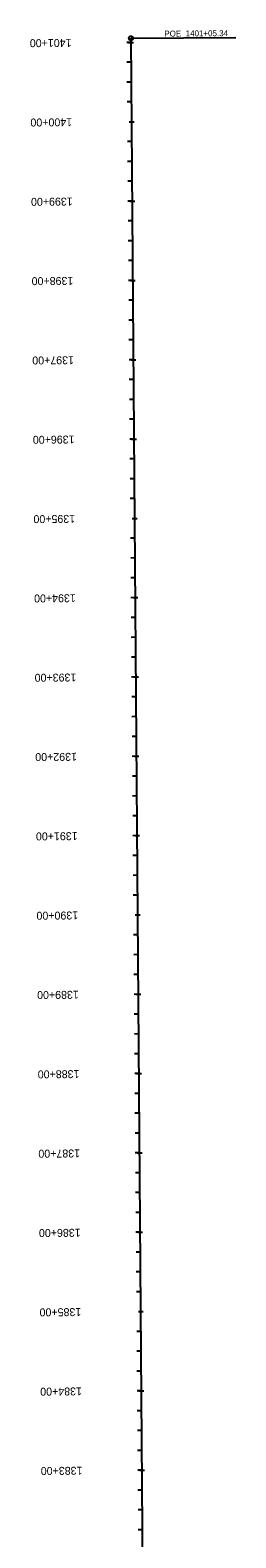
# Model space of a CAD drawing. Extents: x 19548215 to 19548727, y 7547983 to 7562114.
# Drawn here: x 19548234 to 19548493, y 7560213 to 7562114 of the extents above; entities that cross this region are included whole.
import ezdxf

# ---------------------------------------------------------------- set-up
doc = ezdxf.new("R2010")
doc.units = 0
for name, color, linetype in [('Contours Major', 7, 'Continuous'), ('Contours Minor', 7, 'Continuous'), ('TextAlignment', 7, 'Continuous'), ('TextAlignmentSml', 7, 'Continuous')]:
    doc.layers.add(name, color=color, linetype=linetype)

msp = doc.modelspace()

# ---------------------------------------------------------------- linework, layer by layer
at = {"layer": 'Contours Major'}
for p, q in [((19548360.7, 7562098.6), (19548355.3, 7562098.5)), ((19548358.4, 7561998.5), (19548364.5, 7561998.6)), ((19548362.3, 7561898.6), (19548356.8, 7561898.5)), ((19548363, 7561798.6), (19548357.6, 7561798.5)), ((19548363.8, 7561698.6), (19548358.3, 7561698.5)), ((19548364.6, 7561598.6), (19548359.1, 7561598.5)), ((19548362.3, 7561498.5), (19548368.4, 7561498.6)), ((19548366.1, 7561398.6), (19548360.6, 7561398.5)), ((19548366.9, 7561298.6), (19548361.4, 7561298.5)), ((19548367.6, 7561198.6), (19548362.2, 7561198.5)), ((19548368.4, 7561098.6), (19548363, 7561098.5)), ((19548366.1, 7560998.6), (19548372.2, 7560998.6)), ((19548370, 7560898.6), (19548364.5, 7560898.5)), ((19548370.7, 7560798.6), (19548365.3, 7560798.6)), ((19548371.5, 7560698.6), (19548366, 7560698.6)), ((19548372.3, 7560598.6), (19548366.8, 7560598.6)), ((19548370, 7560498.6), (19548376.1, 7560498.6)), ((19548373.8, 7560398.6), (19548368.3, 7560398.6)), ((19548374.6, 7560298.6), (19548369.1, 7560298.6))]:
    msp.add_line(p, q, dxfattribs=at)
at = {"layer": 'Contours Minor'}
msp.add_line((19548386.5, 7558748.2), (19548360.7, 7562103.9), dxfattribs=at)
at = {"layer": 'TextAlignment'}
for p in [(19548360.7, 7562103.9), (19548492.7, 7562104.9)]:
    msp.add_line(p, (19548492.7, 7562104.9), dxfattribs=at)
msp.add_circle((19548360.7, 7562103.9), 2.67, dxfattribs=at)
at = {"layer": 'TextAlignmentSml'}
for p, q in [((19548357.7, 7562098.5), (19548363.8, 7562098.6)), ((19548360.9, 7562073.6), (19548355.4, 7562073.5)), ((19548361.1, 7562048.6), (19548355.6, 7562048.5)), ((19548361.3, 7562023.6), (19548355.8, 7562023.5)), ((19548358.4, 7561998.5), (19548364.5, 7561998.6)), ((19548361.7, 7561973.6), (19548356.2, 7561973.5)), ((19548361.9, 7561948.6), (19548356.4, 7561948.5)), ((19548362.1, 7561923.6), (19548356.6, 7561923.5)), ((19548359.2, 7561898.5), (19548365.3, 7561898.6)), ((19548362.4, 7561873.6), (19548357, 7561873.5)), ((19548362.6, 7561848.6), (19548357.2, 7561848.5)), ((19548362.8, 7561823.6), (19548357.4, 7561823.5)), ((19548360, 7561798.5), (19548366.1, 7561798.6)), ((19548363.2, 7561773.6), (19548357.8, 7561773.5)), ((19548363.4, 7561748.6), (19548358, 7561748.5)), ((19548363.6, 7561723.6), (19548358.1, 7561723.5)), ((19548360.7, 7561698.5), (19548366.9, 7561698.6)), ((19548364, 7561673.6), (19548358.5, 7561673.5)), ((19548364.2, 7561648.6), (19548358.7, 7561648.5)), ((19548364.4, 7561623.6), (19548358.9, 7561623.5)), ((19548361.5, 7561598.5), (19548367.6, 7561598.6)), ((19548364.8, 7561573.6), (19548359.3, 7561573.5)), ((19548365, 7561548.6), (19548359.5, 7561548.5)), ((19548365.1, 7561523.6), (19548359.7, 7561523.5)), ((19548362.3, 7561498.5), (19548368.4, 7561498.6)), ((19548365.5, 7561473.6), (19548360.1, 7561473.5)), ((19548365.7, 7561448.6), (19548360.3, 7561448.5)), ((19548365.9, 7561423.6), (19548360.5, 7561423.5)), ((19548363, 7561398.6), (19548369.2, 7561398.6)), ((19548366.3, 7561373.6), (19548360.8, 7561373.5)), ((19548366.5, 7561348.6), (19548361, 7561348.5)), ((19548366.7, 7561323.6), (19548361.2, 7561323.5)), ((19548363.8, 7561298.6), (19548369.9, 7561298.6)), ((19548367.1, 7561273.6), (19548361.6, 7561273.5)), ((19548367.3, 7561248.6), (19548361.8, 7561248.5)), ((19548367.5, 7561223.6), (19548362, 7561223.5)), ((19548364.6, 7561198.6), (19548370.7, 7561198.6)), ((19548367.8, 7561173.6), (19548362.4, 7561173.5)), ((19548368, 7561148.6), (19548362.6, 7561148.5)), ((19548368.2, 7561123.6), (19548362.8, 7561123.5)), ((19548365.4, 7561098.6), (19548371.5, 7561098.6)), ((19548368.6, 7561073.6), (19548363.1, 7561073.5)), ((19548368.8, 7561048.6), (19548363.3, 7561048.5)), ((19548369, 7561023.6), (19548363.5, 7561023.5)), ((19548366.1, 7560998.6), (19548372.2, 7560998.6)), ((19548369.4, 7560973.6), (19548363.9, 7560973.5)), ((19548369.6, 7560948.6), (19548364.1, 7560948.5)), ((19548369.8, 7560923.6), (19548364.3, 7560923.5)), ((19548366.9, 7560898.6), (19548373, 7560898.6)), ((19548370.1, 7560873.6), (19548364.7, 7560873.5)), ((19548370.3, 7560848.6), (19548364.9, 7560848.5)), ((19548370.5, 7560823.6), (19548365.1, 7560823.5)), ((19548367.7, 7560798.6), (19548373.8, 7560798.6)), ((19548370.9, 7560773.6), (19548365.5, 7560773.6)), ((19548371.1, 7560748.6), (19548365.6, 7560748.6)), ((19548371.3, 7560723.6), (19548365.8, 7560723.6)), ((19548368.4, 7560698.6), (19548374.6, 7560698.6)), ((19548371.7, 7560673.6), (19548366.2, 7560673.6)), ((19548371.9, 7560648.6), (19548366.4, 7560648.6)), ((19548372.1, 7560623.6), (19548366.6, 7560623.6)), ((19548369.2, 7560598.6), (19548375.3, 7560598.6)), ((19548372.5, 7560573.6), (19548367, 7560573.6)), ((19548372.6, 7560548.6), (19548367.2, 7560548.6)), ((19548372.8, 7560523.6), (19548367.4, 7560523.6)), ((19548370, 7560498.6), (19548376.1, 7560498.6)), ((19548373.2, 7560473.6), (19548367.8, 7560473.6)), ((19548373.4, 7560448.6), (19548368, 7560448.6)), ((19548373.6, 7560423.6), (19548368.2, 7560423.6)), ((19548370.7, 7560398.6), (19548376.9, 7560398.6)), ((19548374, 7560373.6), (19548368.5, 7560373.6)), ((19548374.2, 7560348.6), (19548368.7, 7560348.6)), ((19548374.4, 7560323.6), (19548368.9, 7560323.6)), ((19548371.5, 7560298.6), (19548377.6, 7560298.6)), ((19548374.8, 7560273.6), (19548369.3, 7560273.6)), ((19548375, 7560248.6), (19548369.5, 7560248.6)), ((19548375.1, 7560223.6), (19548369.7, 7560223.6))]:
    msp.add_line(p, q, dxfattribs=at)

# ---------------------------------------------------------------- texts
at = {"layer": 'Contours Major'}
for s, p in [('1400+00', (19548286.5, 7562003)), ('1395+00', (19548290.3, 7561503)), ('1390+00', (19548294.1, 7561003)), ('1385+00', (19548298, 7560503))]:
    msp.add_text(s, height=10.02, rotation=180.441, dxfattribs=at).set_placement(p)
at = {"layer": 'TextAlignment'}
for s, p in [('POE ', (19548402.7, 7562105.9)), ('1401+05.34', (19548429.6, 7562106.1))]:
    msp.add_text(s, height=7.5, rotation=0.441, dxfattribs=at).set_placement(p)
at = {"layer": 'TextAlignmentSml'}
for s, p in [('1401+00', (19548285.7, 7562103)), ('1400+00', (19548286.5, 7562003)), ('1399+00', (19548287.2, 7561903)), ('1398+00', (19548288, 7561803)), ('1397+00', (19548288.8, 7561703)), ('1396+00', (19548289.5, 7561603)), ('1395+00', (19548290.3, 7561503)), ('1394+00', (19548291.1, 7561403)), ('1393+00', (19548291.8, 7561303)), ('1392+00', (19548292.6, 7561203)), ('1391+00', (19548293.4, 7561103)), ('1390+00', (19548294.1, 7561003)), ('1389+00', (19548294.9, 7560903)), ('1388+00', (19548295.7, 7560803)), ('1387+00', (19548296.5, 7560703)), ('1386+00', (19548297.2, 7560603)), ('1385+00', (19548298, 7560503)), ('1384+00', (19548298.8, 7560403)), ('1383+00', (19548299.5, 7560303))]:
    msp.add_text(s, height=10.02, rotation=180.441, dxfattribs=at).set_placement(p)

doc.saveas('drawing.dxf')
